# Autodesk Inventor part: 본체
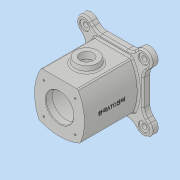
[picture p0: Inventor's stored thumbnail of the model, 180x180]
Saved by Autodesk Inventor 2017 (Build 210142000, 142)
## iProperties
Part Number: 본체
Material: 일반
Document SubType Name: Modeling
Designer: Administrator
Density: 1 g/cm^3
Appearance: 기본값
Author: Administrator
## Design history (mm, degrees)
sketch "스케치1"
  geometry: L1 (-53, 53)-(53, 53); L2 (53, 53)-(53, -53); L3 (53, -53)-(-53, -53); L4 (-53, -53)-(-53, 53); L5 (-53, 53)-(53, -53); L6 (53, 53)-(-53, -53); 1 further point
  constraints: 12 end point, 2 midpoint, 2 parallel, 1 horizontal, 1 perpendicular
  dimensions: "d0" = 106 distance of L1.end L2.end; "d1" = 106 distance of L1.start L1.end
extrude "돌출1" new body sketch "스케치1" distance "d5" = 12; taper "d6" = 0 deg
sketch "스케치2"
  geometry: L1 (53, 53)-(-53, 53) reference; L2 (0, 53)-(0, 0); L3 (-53.033, 53.033)-(0, 0); L4 (-63.64, 42.426)-(-44.143, 22.93); L5 (-42.426, 63.64)-(-22.93, 44.143); L6 (-44.143, 22.93)-(-22.93, 44.143); A1 r 15 centre (-53.033, 53.033) between (-42.426, 63.64) and (-63.64, 42.426)
  constraints: 10 end point, 2 parallel, 2 point on circle, 2 tangent, 1 centre point, 1 coincident, 1 midpoint, 1 vertical
  dimensions: "d87" = 30 diameter of A1; "d88" = 45 deg angle of L2 L3; "d89" = 75 distance of L3.start L3.end; "d90" = 21.2132 horizontal distance of L4.end L5.end; "d91" = 19.49686 horizontal distance of L5.start L5.end
extrude "돌출2" join sketch "스케치2" distance "d10" = 12; taper "d11" = 0 deg
sketch "스케치3"
  geometry: L1 (-45, 45)-(-32.942, 45); L2 (45, 45)-(45, -45); L3 (45, -45)-(-45, -45); L4 (-45, -45)-(-45, 45); L5 (-45, 45)-(45, -45); L6 (45, 45)-(-45, -45); L7 (-45, 0)-(45, 0); L8 (32.942, 45)-(45, 45); L9 (-32.942, 45)-(32.942, 45); A1 r 90 centre (0, 45) between (-45, -32.942) and (-37.029, -37.029); A2 r 90 centre (45, 0) between (-32.942, 45) and (-37.029, -37.029); A3 r 90 centre (-45, 0) between (32.942, -45) and (37.029, -37.029); A4 r 90 centre (0, 45) between (-37.029, -37.029) and (37.029, -37.029); A5 r 90 centre (45, 0) between (-37.029, -37.029) and (-32.942, -45); A6 r 90 centre (-45, 0) between (37.029, -37.029) and (32.942, 45); A7 r 90 centre (0, 45) between (37.029, -37.029) and (45, -32.942); 4 further points
  constraints: 18 end point, 18 point on circle, 7 centre point, 5 midpoint, 5 point on line, 5 tangent, 4 horizontal, 4 parallel, 3 perpendicular, 2 horizontal alignment, 1 vertical alignment
  dimensions: "d15" = 90 distance of L2.start L2.end; "d16" = 90 distance of L1.start L2.start; "d17" = 90 radius of A1; "d18" = 90 radius of A2; "d19" = 90 radius of A3; "d20" = 90 distance of L7.start L7.end
extrude "돌출3" join sketch "스케치3" distance "d21" = 98; taper "d22" = 0 deg
node "작업 평면1"
sketch "스케치4"
  geometry: L1 (31.787, 0)-(-31.787, 0) reference; C1 r 20 at (0, 61); 1 further point
  constraints: 1 centre point, 1 vertical alignment
  dimensions: "d24" = 40 diameter of C1; "d25" = 61 distance from line of L1 C1.centre
extrude "돌출4" join sketch "스케치4" stored distance "d26" = 98; taper "d27" = 10 deg
sketch "스케치5"
  geometry: C1 r 25 at (0, 0); 1 further point
  constraints: 1 centre point, 1 coincident
  dimensions: "d28" = 50 diameter of C1
extrude "돌출5" cut sketch "스케치5" distance "d29" = 12; taper "d30" = 0 deg
sketch "스케치6"
  geometry: C1 r 37 at (0, 0); 1 further point
  constraints: 1 centre point, 1 coincident
  dimensions: "d31" = 74 diameter of C1
extrude "돌출6" cut sketch "스케치6" distance "d32" = 86; taper "d33" = 0 deg
sketch "스케치7"
  geometry: C1 r 25 at (0, 0); 1 further point
  constraints: 1 centre point, 1 coincident
  dimensions: "d34" = 50 diameter of C1
extrude "돌출7" cut sketch "스케치7" stored distance "d35" = 86; taper "d36" = 0 deg
sketch "스케치8"
  geometry: C1 r 20 at (0, 0) reference; C2 r 12 at (0, 0); 1 further point
  constraints: 1 centre point, 1 coincident
  dimensions: "d37" = 24 diameter of C2
extrude "돌출8" cut sketch "스케치8" distance "d38" = 13; taper "d39" = 0 deg
sketch "스케치9"
  geometry: C1 r 12 at (0, 0) reference; C2 r 15 at (0, 0); 1 further point
  constraints: 1 centre point, 1 coincident
  dimensions: "d40" = 30 diameter of C2
extrude "돌출9" cut sketch "스케치9" stored distance "d41" = 13; taper "d42" = 0 deg
fillet "모깎기1" dims "d43" = 20
sketch "스케치10"
  geometry: L1 (0, 40)-(0, 0); L2 (0, 0)-(-28.284, 28.284); A1 r 40 centre (0, 0) between (0, 40) and (-28.284, 28.284); 2 further points
  constraints: 4 end point, 2 coincident, 2 point on circle, 1 centre point, 1 vertical
  dimensions: "d44" = 80 diameter of A1; "d45" = 45 deg angle of L1 L2
hole "구멍1" sketch "스케치10" at (-28.284, 28.284) diameter "d46" = 3.242; stored, may be unused: countersink angle "d50" = 90 deg, drill point angle "d52" = 118 deg; dims "d47" = 9, "d48" = 4, "d49" = 2, "d51" = 11
sketch "스케치11"
  geometry: L1 (-32.942, 45)-(32.942, 45) reference; L2 (23.503, 53)-(-23.503, 53) reference; L3 (-53, 23.503)-(-53, -23.503) reference; L4 (-23.503, -53)-(23.503, -53) reference; L5 (53, -23.503)-(53, 23.503) reference; L6 (-37.645, 58.858)-(-42.426, 63.64) reference; L7 (-63.64, 42.426)-(-58.858, 37.645) reference; L8 (-58.858, -37.645)-(-63.64, -42.426) reference; L9 (-42.426, -63.64)-(-37.645, -58.858) reference; L10 (37.645, -58.858)-(42.426, -63.64) reference; L11 (63.64, -42.426)-(58.858, -37.645) reference; L12 (58.858, 37.645)-(63.64, 42.426) reference; L13 (42.426, 63.64)-(37.645, 58.858) reference; A1 r 90 centre (-45, 0) between (37.029, -37.029) and (32.942, 45) reference; A2 r 90 centre (0, 45) between (-37.029, -37.029) and (37.029, -37.029) reference; A3 r 90 centre (45, 0) between (-32.942, 45) and (-37.029, -37.029) reference; A4 r 15 centre (-53.033, 53.033) between (-42.426, 63.64) and (-63.64, 42.426) reference; A5 r 15 centre (-53.033, -53.033) between (-63.64, -42.426) and (-42.426, -63.64) reference; A6 r 15 centre (53.033, -53.033) between (42.426, -63.64) and (63.64, -42.426) reference; A7 r 15 centre (53.033, 53.033) between (63.64, 42.426) and (42.426, 63.64) reference; A8 r 20 centre (-73, 23.503) between (-53, 23.503) and (-58.858, 37.645) reference; A9 r 20 centre (-73, -23.503) between (-58.858, -37.645) and (-53, -23.503) reference; A10 r 20 centre (-23.503, -73) between (-23.503, -53) and (-37.645, -58.858) reference; A11 r 20 centre (-23.503, 73) between (-37.645, 58.858) and (-23.503, 53) reference; A12 r 20 centre (23.503, -73) between (37.645, -58.858) and (23.503, -53) reference; A13 r 20 centre (73, -23.503) between (53, -23.503) and (58.858, -37.645) reference; A14 r 20 centre (73, 23.503) between (58.858, 37.645) and (53, 23.503) reference; A15 r 20 centre (23.503, 73) between (23.503, 53) and (37.645, 58.858) reference; 5 further points
hole "구멍2" sketch "스케치11" at (-53, 53), (53, 53), (-53, -53), (53, -53) diameter "d56" = 9; stored, may be unused: countersink angle "d60" = 90 deg, drill point angle "d62" = 118 deg; dims "d57" = 9, "d58" = 18, "d59" = 2, "d61" = 11
node "작업 평면2"
sketch "스케치12"
  geometry: L1 (31.787, 0)-(-31.787, 0) reference; L2 (55, 81)-(55, 41) reference; 4 further points
  constraints: 1 other
  dimensions: "d64" = 61 distance from line of L1 point (0, 61); "d65" = 55 distance from line of L2 point (0, 61)
feature "엠보싱1" sketch "스케치12" dims "d0" = 106, "d1" = 106, "d15" = 90, "d16" = 90, "d17" = 90, "d18" = 90, "d19" = 90, "d20" = 90, "d66" = 0.5, "d67" = 0
sketch "스케치13"
  geometry: L1 (40, 0)-(0, 0); L2 (0, 0)-(28.284, 28.284); C1 r 1.621 at (28.284, 28.284) reference; A1 r 40 centre (0, 0) between (40, 0) and (28.284, 28.284); 2 further points
  constraints: 4 end point, 2 coincident, 2 point on circle, 1 centre point, 1 horizontal
  dimensions: "d69" = 80 diameter of A1; "d70" = 45 deg angle of L1 L2
hole "구멍3" sketch "스케치13" at (28.284, 28.284) diameter "d71" = 3.242; stored, may be unused: countersink angle "d75" = 90 deg, drill point angle "d77" = 118 deg; dims "d72" = 9, "d73" = 18, "d74" = 2, "d76" = 11
fillet "모깎기3" dims "d81" = 3
chamfer "모따기1" distance "d82" = 1; stored, may be unused: second distance "d83" = 2, angle "d84" = 45 deg
fillet "모깎기5" dims "d92" = 3
fillet "모깎기6" dims "d93" = 3
fillet "모깎기7" dims "d94" = 3
fillet "모깎기8" dims "d95" = 3
node "솔리드1"
pattern_circular "원형 패턴1" dims angle "d13" = 360 deg
pattern_circular "원형 패턴2" dims angle "d54" = 360 deg
pattern_circular "원형 패턴3" dims angle "d79" = 360 deg
node "투영된 루프1"
node "투영된 루프2"
other parameters: "d23" = 55, "d63" = 129.5
